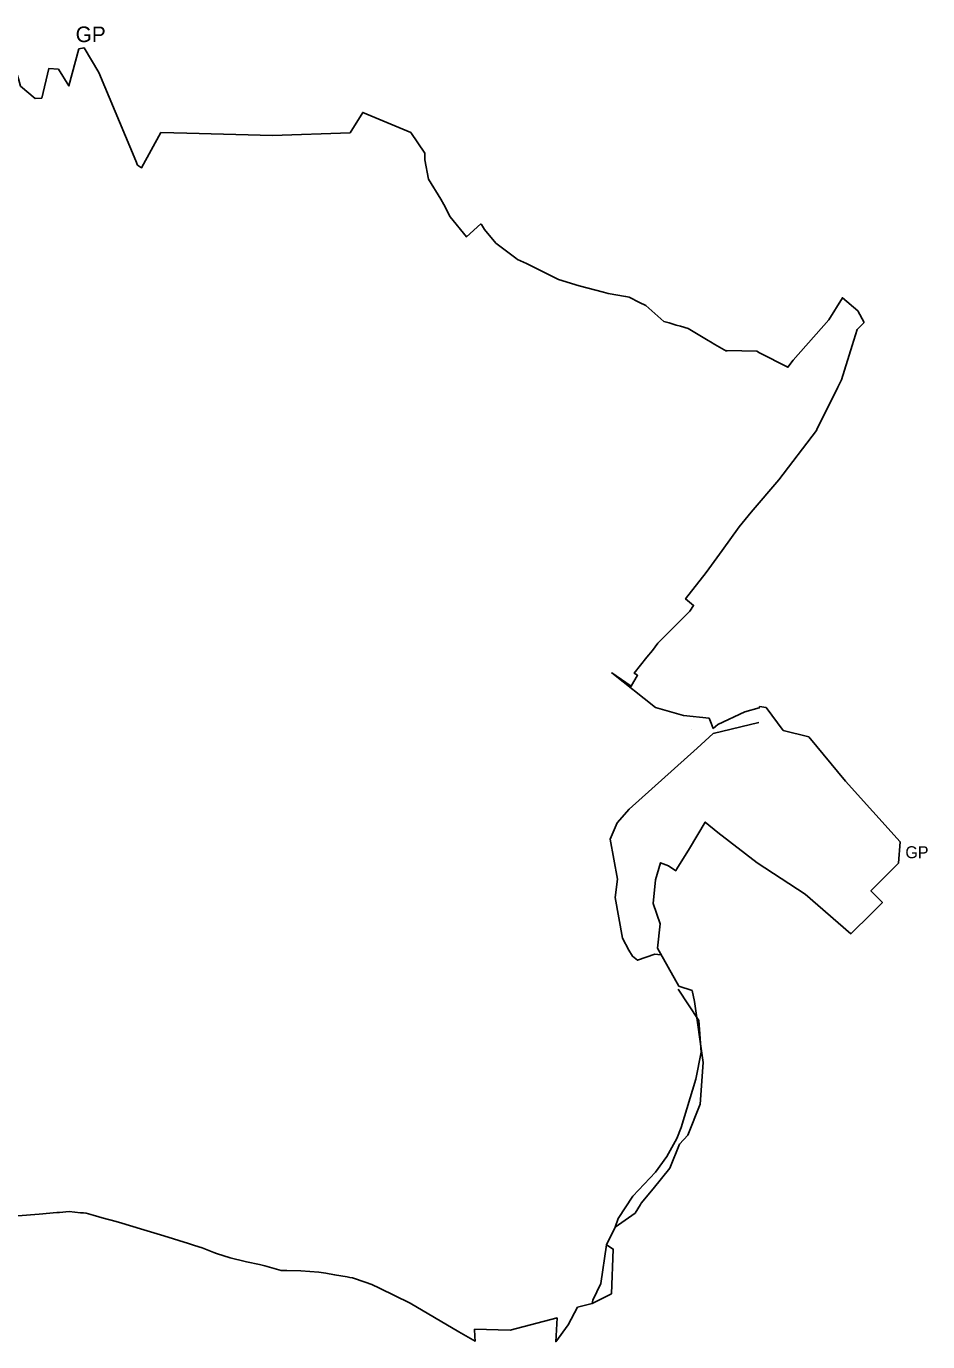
# Model space of a CAD drawing. Extents: x -584576 to -579722, y -1113169 to -1110375.
# Drawn here: x -581887 to -581308, y -1113169 to -1112324 of the extents above; entities that cross this region are included whole.
import ezdxf

# ---------------------------------------------------------------- set-up
doc = ezdxf.new("R2010")
doc.units = 0
for name, color, linetype in [('Level 255', 7, 'Continuous'), ('OVNE_SET', 7, 'Continuous'), ('OVNI_SET', 7, 'Continuous'), ('VODA', 7, 'Continuous')]:
    doc.layers.add(name, color=color, linetype=linetype)

msp = doc.modelspace()

# ---------------------------------------------------------------- linework, layer by layer
at = {"layer": 'Level 255'}
for p, q in [((-581467.95, -1112942.41), (-581467.95, -1112942.41)), ((-581538.68, -1113158.08), (-581538.68, -1113158.08)), ((-581538.68, -1113158.08), (-581538.68, -1113158.08)), ((-581538.68, -1113158.08), (-581538.68, -1113158.08))]:
    msp.add_line(p, q, dxfattribs=at)
at = {"layer": 'OVNE_SET'}
msp.add_line((-581459.53, -1112775.75), (-581459.53, -1112775.75), dxfattribs=at)
msp.add_line((-581459.53, -1112775.75), (-581459.53, -1112775.75), dxfattribs=at)
for points in [[(-581348.65, -1112514.08), (-581353.17, -1112518.72), (-581356.27, -1112528.84)], [(-581356.27, -1112528.84), (-581363.08, -1112551.04), (-581365.39, -1112555.69), (-581378.89, -1112582.9), (-581379.18, -1112583.48), (-581403.35, -1112615.21), (-581421.09, -1112635.98), (-581428.79, -1112645.41), (-581439.81, -1112660.64)], [(-581439.81, -1112660.64), (-581450, -1112674.87), (-581463.23, -1112691.71), (-581458.11, -1112695.87), (-581460.46, -1112699.62), (-581481.16, -1112720.17), (-581484.57, -1112724.95), (-581488.03, -1112729.11), (-581496.32, -1112739.35), (-581494.04, -1112740.76), (-581498.11, -1112747.89), (-581510.7, -1112739.27), (-581482.47, -1112761.58), (-581464.61, -1112766.56), (-581448.05, -1112768.43)], [(-581445.45, -1112775.11), (-581442.53, -1112772.45), (-581425.13, -1112764.2), (-581415.95, -1112761.8), (-581415.74, -1112760.89), (-581411.58, -1112761.61), (-581400.67, -1112776.21)], [(-581448.05, -1112768.43), (-581446.82, -1112771.6), (-581445.45, -1112775.11)], [(-581400.67, -1112776.21), (-581384.17, -1112780.27), (-581360.66, -1112808.82), (-581325.55, -1112847.92), (-581326.43, -1112861.49)], [(-581326.43, -1112861.49), (-581344.23, -1112879.21), (-581336.9, -1112886.82), (-581343.93, -1112893.8), (-581357.18, -1112906.93), (-581386.48, -1112881.45), (-581417.3, -1112861.26), (-581442.53, -1112841.88), (-581450.61, -1112835.14), (-581460.76, -1112852.01), (-581468.87, -1112865.16), (-581469.6, -1112866.36), (-581474.18, -1112863.3), (-581479.46, -1112861.27), (-581482.63, -1112872.2)], [(-581482.63, -1112872.2), (-581483.97, -1112887.34), (-581479.63, -1112900.5), (-581481.3, -1112916.23), (-581467.53, -1112940.49), (-581459.08, -1112943.41), (-581457.56, -1112950.44), (-581452.03, -1112989.67), (-581453.79, -1113016.47), (-581461.78, -1113036.31), (-581467.21, -1113041.97), (-581473.42, -1113057.52), (-581484.04, -1113070.87), (-581491.74, -1113080.04), (-581492.24, -1113080.84), (-581495.72, -1113086.45), (-581508.5, -1113095.43), (-581514.1, -1113106.69), (-581509.74, -1113109.44), (-581510.81, -1113138.19), (-581523.19, -1113144.43), (-581532.59, -1113146.85), (-581538.68, -1113158.08), (-581546.66, -1113168.98), (-581545.74, -1113153.72), (-581575.9, -1113161.57), (-581598.71, -1113160.99)], [(-581859.1, -1113085.41), (-581865.3, -1113085.91), (-581866.14, -1113085.98), (-581867.03, -1113086.05), (-581878.31, -1113086.95), (-581891.97, -1113088.05), (-581910.76, -1113086.29), (-581945.58, -1113087.97), (-581967.16, -1113083.02), (-581981.23, -1113075.79), (-582008.42, -1113071.04), (-582094.16, -1113037.63)], [(-581598.71, -1113160.99), (-581598.49, -1113165.65), (-581598.35, -1113168.64), (-581608.86, -1113162.69), (-581640.08, -1113144.13), (-581659.75, -1113134.69), (-581664.75, -1113132.29), (-581669.1, -1113130.78), (-581677.15, -1113127.99), (-581678.89, -1113127.68), (-581680.63, -1113127.36), (-581688.65, -1113125.93), (-581694.21, -1113125.01), (-581698.85, -1113124.25), (-581710.25, -1113123.38), (-581719.38, -1113123.23), (-581722.94, -1113123.17), (-581733.34, -1113120.3), (-581736.86, -1113119.33), (-581745.24, -1113117.59), (-581746, -1113117.43), (-581755.65, -1113115.03), (-581764.52, -1113112.38), (-581766.09, -1113111.75), (-581773.71, -1113108.7), (-581778.61, -1113107.1), (-581782.48, -1113105.84), (-581798.3, -1113100.97), (-581813.29, -1113096.43), (-581825.29, -1113092.84), (-581828.84, -1113091.85), (-581837.79, -1113089.35), (-581840.13, -1113088.69), (-581843.6, -1113087.72), (-581848.11, -1113086.45), (-581849.84, -1113086.28), (-581851.87, -1113086.09), (-581859.1, -1113085.41)]]:
    msp.add_lwpolyline(points, dxfattribs=at)
at = {"layer": 'OVNI_SET'}
for points in [[(-581865.86, -1112351.32), (-581859.24, -1112362.18), (-581852.78, -1112338.22)], [(-581852.78, -1112338.22), (-581849.45, -1112337.65), (-581840.09, -1112353.56)], [(-581916.37, -1112383.89), (-581892.2, -1112355.44), (-581891.54, -1112357.67), (-581890.22, -1112362.21), (-581880.91, -1112370.27)], [(-581880.91, -1112370.27), (-581876.68, -1112370.01), (-581872.04, -1112350.93), (-581865.86, -1112351.32)], [(-581840.09, -1112353.56), (-581816.35, -1112410.23), (-581815.27, -1112413.07)], [(-581728.46, -1112393.9), (-581678.65, -1112392.2), (-581670.5, -1112379.15), (-581639.69, -1112392.12)], [(-581815.27, -1112413.07), (-581812.56, -1112414.72), (-581800.19, -1112392.05)], [(-581800.19, -1112392.05), (-581783.58, -1112392.48), (-581728.46, -1112393.9)], [(-581639.69, -1112392.12), (-581630.63, -1112405.3), (-581630.77, -1112409.71), (-581628.28, -1112421.99), (-581620.38, -1112434.89), (-581618.58, -1112438.3), (-581614.4, -1112446.24)], [(-581614.4, -1112446.24), (-581603.88, -1112459.12), (-581594.68, -1112450.78), (-581594.34, -1112451.28), (-581592.27, -1112454.36), (-581585.09, -1112463.28), (-581572.15, -1112472.81), (-581571.1, -1112473.58)], [(-581571.1, -1112473.58), (-581565.36, -1112476.34), (-581557.71, -1112480.02), (-581544.81, -1112486.42), (-581531.6, -1112490.69), (-581516.01, -1112494.68), (-581512.86, -1112495.58)], [(-581512.86, -1112495.58), (-581501.8, -1112497.38), (-581500.5, -1112497.68), (-581499.46, -1112497.92), (-581492.91, -1112501.21), (-581488.68, -1112503.33), (-581477.18, -1112513.48), (-581473.87, -1112514.45), (-581471.77, -1112515.1), (-581469.26, -1112515.87), (-581466.6, -1112516.58), (-581461.5, -1112518.05), (-581448.76, -1112525.63)], [(-581371.32, -1112512.37), (-581362.54, -1112498.26), (-581352.72, -1112506.71), (-581348.65, -1112514.08)], [(-581415.7, -1112533.68), (-581397.5, -1112542.94), (-581394.22, -1112538.38), (-581371.32, -1112512.37)], [(-581448.76, -1112525.63), (-581447.27, -1112526.52), (-581444.52, -1112528.22), (-581437.03, -1112532.52), (-581436.83, -1112532.17), (-581417.48, -1112532.54), (-581415.7, -1112533.68)]]:
    msp.add_lwpolyline(points, dxfattribs=at)
at = {"layer": 'VODA'}
for p, q in [((-581408.61, -1112765.06), (-581408.61, -1112765.06)), ((-581408.61, -1112765.06), (-581408.61, -1112765.06)), ((-581506.53, -1112835.62), (-581506.53, -1112835.62)), ((-581517.7, -1113131.51), (-581522.88, -1113142.23)), ((-581517.7, -1113131.51), (-581517.7, -1113131.51)), ((-581522.88, -1113142.23), (-581523.19, -1113144.43)), ((-581538.68, -1113158.08), (-581546.66, -1113168.98))]:
    msp.add_line(p, q, dxfattribs=at)
for points in [[(-581416.12, -1112771.15), (-581445.45, -1112778.15), (-581455.85, -1112787.58), (-581499.41, -1112826.93)], [(-581499.41, -1112826.93), (-581507.21, -1112835.71), (-581511.76, -1112846.12), (-581507.02, -1112871.83), (-581508.4, -1112883.58), (-581503.73, -1112909.81), (-581499.76, -1112917.4), (-581497.37, -1112921.28), (-581494.05, -1112923.85), (-581483.04, -1112920.07), (-581479.11, -1112920.38)], [(-581467.95, -1112942.41), (-581454.68, -1112962.67), (-581453.27, -1112983.04)], [(-581453.27, -1112983.04), (-581456.66, -1113000.31), (-581466.03, -1113031.44), (-581468.92, -1113038.37), (-581475.24, -1113049.9), (-581482.55, -1113060.15), (-581497.02, -1113075.47), (-581506.44, -1113089.8), (-581508.5, -1113095.43)], [(-581508.5, -1113095.43), (-581514.1, -1113106.69), (-581517.7, -1113131.51)]]:
    msp.add_lwpolyline(points, dxfattribs=at)

# ---------------------------------------------------------------- texts
at = {"layer": 'Level 255'}
for height, p in [(10, (-581854.92, -1112333.99)), (7.7, (-581322.13, -1112858.35))]:
    msp.add_text('GP', height=height, dxfattribs=at).set_placement(p)

doc.saveas('drawing.dxf')
